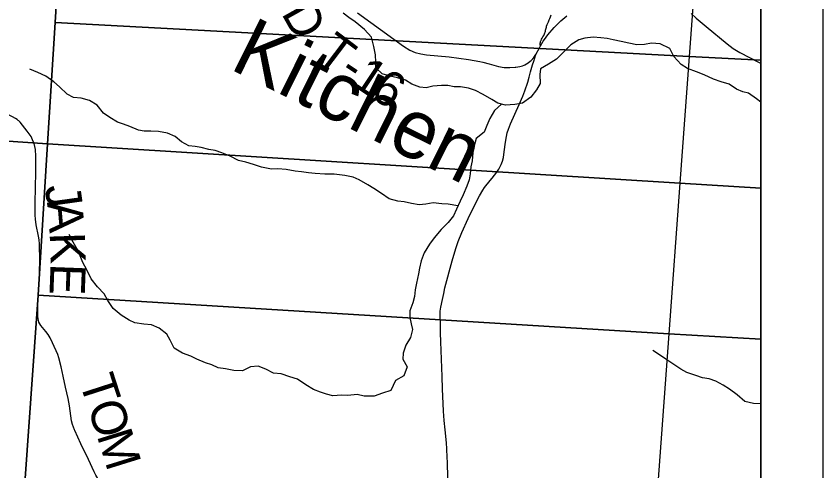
# Model space of a CAD drawing. Extents: x 39.8 to 73.8, y 13 to 35.
# Drawn here: x 47.463 to 48.763, y 31.47 to 32.203 of the extents above; entities that cross this region are included whole.
import ezdxf

# ---------------------------------------------------------------- set-up
doc = ezdxf.new("R2010")
doc.units = 0
for name, color, linetype in [('GM_X_Corporation', 7, 'Continuous'), ('GM_X_Minor_River', 7, 'Continuous'), ('GM_X_Minor_River_Text', 7, 'Continuous'), ('GM_X_Township_Road', 7, 'Continuous'), ('GM_X_Township_Road_Text', 7, 'Continuous'), ('SH_Data', 7, 'Continuous')]:
    doc.layers.add(name, color=color, linetype=linetype)

msp = doc.modelspace()

# ---------------------------------------------------------------- linework, layer by layer
at = {"layer": 'GM_X_Corporation'}
msp.add_lwpolyline([(47.095, 27.8783), (47.5149, 27.8498), (47.5414, 27.8484), (48.663, 27.7809), (48.663, 33.865), (43.6158, 33.865)], dxfattribs=at)
for points in [[(47.5774, 33.0099), (47.5501, 32.582), (47.5261, 32.1933), (47.514, 31.9975), (46.4973, 32.0662), (46.5718, 33.0824)], [(47.5501, 32.582), (48.5754, 32.5153), (48.5476, 32.1383), (47.5261, 32.1933)], [(48.663, 32.1321), (48.663, 32.5097), (48.5754, 32.5153), (48.5476, 32.1383)], [(48.5476, 32.1383), (48.5326, 31.9341), (47.514, 31.9975), (47.5261, 32.1933)], [(48.663, 31.9259), (48.663, 32.1321), (48.5476, 32.1383), (48.5326, 31.9341)], [(46.4973, 32.0662), (47.514, 31.9975), (47.4987, 31.7536), (47.4692, 31.3373), (47.4415, 30.9593), (47.2622, 30.9716), (46.8571, 31.0001), (46.4309, 31.0306)], [(48.5326, 31.9341), (48.5148, 31.6913), (47.4987, 31.7536), (47.514, 31.9975)], [(48.663, 31.6829), (48.663, 31.9259), (48.5326, 31.9341), (48.5148, 31.6913)], [(47.4987, 31.7536), (48.5148, 31.6913), (48.4841, 31.2738), (47.4692, 31.3373)], [(48.663, 31.2629), (48.663, 31.6829), (48.5148, 31.6913), (48.4841, 31.2738)]]:
    msp.add_lwpolyline(points, close=True, dxfattribs=at)
at = {"layer": 'GM_X_Minor_River'}
for p, q in [((47.4985, 32.1125), (47.4856, 32.1181)), ((47.511, 32.1068), (47.4985, 32.1125)), ((47.5239, 32.0974), (47.511, 32.1068)), ((47.5334, 32.0894), (47.5239, 32.0974)), ((47.5456, 32.0773), (47.5334, 32.0894)), ((47.5555, 32.0724), (47.5456, 32.0773)), ((47.568, 32.0713), (47.5555, 32.0724)), ((47.5816, 32.0672), (47.568, 32.0713)), ((47.5938, 32.0597), (47.5816, 32.0672)), ((47.604, 32.0468), (47.5938, 32.0597)), ((48.2341, 32.0511), (48.2266, 32.0385)), ((48.2453, 32.0614), (48.2341, 32.0511)), ((47.6143, 32.04), (47.604, 32.0468)), ((47.6268, 32.0325), (47.6143, 32.04)), ((48.2266, 32.0385), (48.2217, 32.0268)), ((47.6363, 32.0294), (47.6268, 32.0325)), ((47.6466, 32.0253), (47.6363, 32.0294)), ((47.6602, 32.0197), (47.6466, 32.0253)), ((48.2217, 32.0268), (48.2172, 32.0165)), ((47.6697, 32.0178), (47.6602, 32.0197)), ((47.6803, 32.0178), (47.6697, 32.0178)), ((47.6928, 32.0175), (47.6803, 32.0178)), ((47.7072, 32.0145), (47.6928, 32.0175)), ((47.7193, 32.0092), (47.7072, 32.0145)), ((48.2172, 32.0165), (48.2044, 32.0062)), ((47.7296, 32.0005), (47.7193, 32.0092)), ((47.7417, 31.9941), (47.7296, 32.0005)), ((48.2044, 32.0062), (48.2011, 31.9941)), ((47.7516, 31.9934), (47.7417, 31.9941)), ((47.7614, 31.9915), (47.7516, 31.9934)), ((47.7736, 31.9885), (47.7614, 31.9915)), ((47.7842, 31.9867), (47.7736, 31.9885)), ((47.7948, 31.9829), (47.7842, 31.9867)), ((48.2011, 31.9941), (48.1992, 31.9834)), ((47.8081, 31.9776), (47.7948, 31.9829)), ((47.8214, 31.9709), (47.8081, 31.9776)), ((48.1992, 31.9834), (48.1978, 31.9702)), ((47.8335, 31.9679), (47.8214, 31.9709)), ((47.8456, 31.9641), (47.8335, 31.9679)), ((47.8585, 31.96), (47.8456, 31.9641)), ((47.8748, 31.9566), (47.8585, 31.96)), ((48.1959, 31.9607), (48.1948, 31.9493)), ((48.1978, 31.9702), (48.1959, 31.9607)), ((47.885, 31.9574), (47.8748, 31.9566)), ((47.8983, 31.9559), (47.885, 31.9574)), ((47.9131, 31.9533), (47.8983, 31.9559)), ((47.9233, 31.9522), (47.9131, 31.9533)), ((47.9343, 31.9507), (47.9233, 31.9522)), ((47.9449, 31.9496), (47.9343, 31.9507)), ((47.9608, 31.9485), (47.9449, 31.9496)), ((47.9756, 31.9486), (47.9608, 31.9485)), ((47.993, 31.9467), (47.9756, 31.9486)), ((48.0063, 31.9438), (47.993, 31.9467)), ((48.1948, 31.9493), (48.1933, 31.9394)), ((48.0157, 31.9396), (48.0063, 31.9438)), ((48.0298, 31.9313), (48.0157, 31.9396)), ((48.1933, 31.9394), (48.1896, 31.9292)), ((48.0397, 31.9257), (48.0298, 31.9313)), ((48.0518, 31.9173), (48.0397, 31.9257)), ((48.1896, 31.9292), (48.1836, 31.9151)), ((48.0643, 31.909), (48.0518, 31.9173)), ((48.0784, 31.9053), (48.0643, 31.909)), ((48.1836, 31.9151), (48.1787, 31.9052)), ((48.0882, 31.9042), (48.0784, 31.9053)), ((48.1, 31.9012), (48.0882, 31.9042)), ((48.1125, 31.8993), (48.1, 31.9012)), ((48.1231, 31.9001), (48.1125, 31.8993)), ((48.1352, 31.9024), (48.1231, 31.9001)), ((48.1492, 31.901), (48.1352, 31.9024)), ((48.1594, 31.9002), (48.1492, 31.901)), ((48.1751, 31.8975), (48.1594, 31.9002)), ((48.1787, 31.9052), (48.1727, 31.8923)), ((48.1678, 31.8813), (48.1592, 31.871)), ((48.1727, 31.8923), (48.1678, 31.8813)), ((48.1592, 31.871), (48.1483, 31.8592)), ((48.1483, 31.8592), (48.1366, 31.8459)), ((47.5553, 31.8388), (47.5485, 31.8513)), ((48.1366, 31.8459), (48.129, 31.836)), ((47.563, 31.8251), (47.5553, 31.8388)), ((48.129, 31.836), (48.1208, 31.8216)), ((47.5706, 31.8062), (47.563, 31.8251)), ((48.1208, 31.8216), (48.1159, 31.8091)), ((47.5771, 31.7944), (47.5706, 31.8062)), ((48.1159, 31.8091), (48.1129, 31.7973)), ((47.584, 31.7801), (47.5771, 31.7944)), ((48.1129, 31.7973), (48.1114, 31.7878)), ((47.5943, 31.7668), (47.584, 31.7801)), ((48.1114, 31.7878), (48.1081, 31.773)), ((47.6049, 31.7558), (47.5943, 31.7668)), ((48.1081, 31.773), (48.1059, 31.762)), ((47.611, 31.7449), (47.6049, 31.7558)), ((48.1052, 31.7517), (48.1022, 31.7415)), ((48.1059, 31.762), (48.1052, 31.7517)), ((47.6198, 31.7324), (47.611, 31.7449)), ((48.1022, 31.7415), (48.0977, 31.7286)), ((47.6323, 31.7214), (47.6198, 31.7324)), ((48.0977, 31.7286), (48.0977, 31.7176)), ((47.6452, 31.7131), (47.6323, 31.7214)), ((47.6547, 31.7093), (47.6452, 31.7131)), ((48.0977, 31.7176), (48.0997, 31.7077)), ((47.6691, 31.7071), (47.6547, 31.7093)), ((47.6816, 31.7056), (47.6691, 31.7071)), ((47.6938, 31.7007), (47.6816, 31.7056)), ((47.7063, 31.6909), (47.6938, 31.7007)), ((48.0997, 31.7077), (48.1016, 31.6982)), ((47.7113, 31.6811), (47.7063, 31.6909)), ((48.1016, 31.6982), (48.0986, 31.6853)), ((47.7181, 31.6682), (47.7113, 31.6811)), ((48.0911, 31.6732), (48.0866, 31.6603)), ((48.0986, 31.6853), (48.0911, 31.6732)), ((47.7314, 31.6599), (47.7181, 31.6682)), ((48.0866, 31.6603), (48.0863, 31.6504)), ((48.4998, 31.6574), (48.4888, 31.6646)), ((47.7447, 31.6554), (47.7314, 31.6599)), ((47.7546, 31.6505), (47.7447, 31.6554)), ((47.7682, 31.6445), (47.7546, 31.6505)), ((48.0863, 31.6504), (48.0935, 31.6379)), ((48.5115, 31.6495), (48.4998, 31.6574)), ((48.5343, 31.6344), (48.5115, 31.6495)), ((47.7788, 31.6415), (47.7682, 31.6445)), ((47.7887, 31.6366), (47.7788, 31.6415)), ((47.8005, 31.6347), (47.7887, 31.6366)), ((47.8141, 31.6321), (47.8005, 31.6347)), ((47.841, 31.6382), (47.8281, 31.6318)), ((47.8531, 31.6394), (47.841, 31.6382)), ((47.8656, 31.6345), (47.8531, 31.6394)), ((47.8781, 31.6277), (47.8656, 31.6345)), ((48.0935, 31.6379), (48.0879, 31.6238)), ((48.5438, 31.6291), (48.5343, 31.6344)), ((47.8281, 31.6318), (47.8141, 31.6321)), ((47.8902, 31.6266), (47.8781, 31.6277)), ((47.9043, 31.6221), (47.8902, 31.6266)), ((47.9168, 31.6184), (47.9043, 31.6221)), ((48.0879, 31.6238), (48.0743, 31.6162)), ((48.5582, 31.6242), (48.5438, 31.6291)), ((48.5692, 31.6204), (48.5582, 31.6242)), ((47.9301, 31.6093), (47.9168, 31.6184)), ((47.9426, 31.6018), (47.9301, 31.6093)), ((48.0743, 31.6162), (48.0668, 31.5999)), ((48.5798, 31.6186), (48.5692, 31.6204)), ((48.5908, 31.6152), (48.5798, 31.6186)), ((48.6026, 31.6084), (48.5908, 31.6152)), ((48.6125, 31.602), (48.6026, 31.6084)), ((47.9536, 31.5972), (47.9426, 31.6018)), ((47.9631, 31.5942), (47.9536, 31.5972)), ((48.0536, 31.5957), (48.04, 31.5911)), ((48.0668, 31.5999), (48.0536, 31.5957)), ((48.625, 31.5929), (48.6125, 31.602)), ((47.9737, 31.5916), (47.9631, 31.5942)), ((47.9877, 31.5924), (47.9737, 31.5916)), ((47.9979, 31.5921), (47.9877, 31.5924)), ((48.0127, 31.5933), (47.9979, 31.5921)), ((48.0241, 31.591), (48.0127, 31.5933)), ((48.04, 31.5911), (48.0241, 31.591)), ((48.6375, 31.5823), (48.625, 31.5929)), ((48.6512, 31.579), (48.6375, 31.5823)), ((48.663, 31.5784), (48.6512, 31.579))]:
    msp.add_line(p, q, dxfattribs=at)
for points in [[(48.4756, 32.1577), (48.4632, 32.1573), (48.4506, 32.1595), (48.4378, 32.1625), (48.4249, 32.1651), (48.4154, 32.1673), (48.4052, 32.1681), (48.393, 32.1695), (48.3794, 32.1676), (48.3696, 32.1649), (48.3571, 32.1569), (48.3451, 32.1455), (48.3341, 32.1341), (48.3209, 32.1257), (48.3081, 32.1184), (48.307, 32.109), (48.3074, 32.0949), (48.3014, 32.0847), (48.2927, 32.0725), (48.2791, 32.063), (48.2667, 32.061), (48.2515, 32.0598), (48.2394, 32.0628), (48.2299, 32.0689), (48.2155, 32.0772), (48.2033, 32.0836), (48.1923, 32.087), (48.1791, 32.0892), (48.1688, 32.0896), (48.159, 32.0918), (48.1488, 32.0918), (48.1344, 32.0902), (48.1238, 32.0879), (48.1139, 32.089), (48.1007, 32.0935), (48.0908, 32.1003), (48.0779, 32.1041), (48.0658, 32.1067), (48.0529, 32.1104), (48.043, 32.1199), (48.043, 32.1294), (48.0425, 32.1407), (48.0394, 32.1544), (48.0356, 32.1692), (48.0246, 32.182), (48.0097, 32.1941), (47.9995, 32.2009), (47.99, 32.2081)], [(48.663, 32.0649), (48.6559, 32.0699), (48.6434, 32.0793), (48.6339, 32.0815), (48.624, 32.0857), (48.6122, 32.0936), (48.5994, 32.0974), (48.5868, 32.1015), (48.572, 32.1087), (48.5595, 32.1136), (48.5451, 32.1188), (48.5349, 32.1252), (48.5227, 32.1381), (48.5162, 32.1513), (48.5006, 32.1585), (48.487, 32.1596), (48.4756, 32.1577)]]:
    msp.add_lwpolyline(points, dxfattribs=at)
at = {"layer": 'GM_X_Township_Road'}
for points in [[(48.0135, 32.2089), (48.0346, 32.1933), (48.0871, 32.1549), (48.0977, 32.1485), (48.1062, 32.1448), (48.1152, 32.1423), (48.1244, 32.1408), (48.1612, 32.1376), (48.192, 32.1337), (48.2102, 32.1303), (48.2153, 32.1289), (48.2252, 32.1262), (48.2402, 32.1222), (48.2494, 32.1207), (48.2585, 32.1205), (48.2675, 32.1209), (48.2681, 32.121), (48.2748, 32.1219), (48.2789, 32.1231), (48.2815, 32.1242), (48.2828, 32.1248), (48.2881, 32.1278), (48.2916, 32.1306), (48.2932, 32.132), (48.2971, 32.1364), (48.3006, 32.1415), (48.3063, 32.1525), (48.308, 32.1553), (48.3126, 32.1632), (48.3146, 32.1659), (48.3199, 32.1732), (48.33, 32.185), (48.3409, 32.196), (48.3505, 32.2039)], [(48.5508, 32.2078), (48.5587, 32.1998), (48.5751, 32.1864), (48.6086, 32.1586), (48.6186, 32.1513), (48.6292, 32.1448), (48.6595, 32.1292), (48.663, 32.1272)], [(48.308, 32.1553), (48.3077, 32.1568), (48.3076, 32.1584), (48.3077, 32.1598), (48.3079, 32.1611), (48.3082, 32.1623), (48.3087, 32.1637), (48.3089, 32.1642), (48.3099, 32.1663), (48.3107, 32.1678), (48.312, 32.17), (48.3132, 32.172), (48.314, 32.1734), (48.3147, 32.1748), (48.3152, 32.1762), (48.3157, 32.1776), (48.3161, 32.1789), (48.3164, 32.1805), (48.3168, 32.1824), (48.3172, 32.1841), (48.3175, 32.1858), (48.318, 32.1874), (48.3188, 32.1897), (48.3197, 32.192), (48.3207, 32.1942), (48.3223, 32.1975), (48.3233, 32.1997), (48.3243, 32.2022), (48.3255, 32.2054)], [(48.1592, 31.4396), (48.1583, 31.4831), (48.1573, 31.5045), (48.1571, 31.5061), (48.1564, 31.5159), (48.1543, 31.5368), (48.1529, 31.5519), (48.1519, 31.5669), (48.1501, 31.6029), (48.1497, 31.6226), (48.1481, 31.6645), (48.1477, 31.6783), (48.1472, 31.6928), (48.1468, 31.7058), (48.1463, 31.72), (48.1466, 31.7281), (48.1477, 31.7345), (48.1503, 31.7468), (48.1521, 31.7564), (48.1542, 31.7653), (48.1657, 31.8089), (48.1717, 31.829), (48.1757, 31.8403), (48.1816, 31.8546), (48.1918, 31.8773), (48.2029, 31.9004), (48.21, 31.9138), (48.215, 31.9227), (48.218, 31.927), (48.2272, 31.9382), (48.2301, 31.9422), (48.2377, 31.9519), (48.2412, 31.9568), (48.2449, 31.9644), (48.2468, 31.9697), (48.2483, 31.9755), (48.2498, 31.9847), (48.2516, 32), (48.2531, 32.0091), (48.2545, 32.0151), (48.2563, 32.021), (48.2596, 32.0296), (48.2736, 32.0607), (48.2796, 32.0742), (48.2829, 32.0827), (48.2875, 32.0967), (48.29, 32.1051), (48.2904, 32.1071), (48.2922, 32.1136), (48.2932, 32.1173), (48.2954, 32.125), (48.2974, 32.1309), (48.3006, 32.1415)], [(47.4666, 32.0352), (47.465, 32.0365), (47.4625, 32.0382), (47.4573, 32.0412), (47.4491, 32.0453), (47.4348, 32.0515), (47.4205, 32.0571), (47.4061, 32.063), (47.3481, 32.0884)], [(47.5579, 31.5358), (47.5575, 31.5367), (47.5543, 31.5453), (47.5527, 31.5512), (47.5491, 31.5754), (47.5473, 31.5872), (47.543, 31.6053), (47.5392, 31.6232), (47.536, 31.638), (47.5321, 31.6526), (47.5303, 31.6579), (47.522, 31.6766), (47.5179, 31.685), (47.5147, 31.6903), (47.5111, 31.6953), (47.5032, 31.7048), (47.5015, 31.7073), (47.5001, 31.7101), (47.4991, 31.713), (47.4986, 31.716), (47.4984, 31.7191), (47.4985, 31.7283), (47.4983, 31.7376), (47.4984, 31.7438), (47.4991, 31.7531), (47.5004, 31.7748), (47.5013, 31.809), (47.5009, 31.8363), (47.5004, 31.8426), (47.4995, 31.8486), (47.4958, 31.867), (47.4945, 31.8762), (47.4942, 31.8824), (47.4942, 31.8886), (47.4941, 31.8917), (47.4939, 31.8979), (47.4942, 31.901), (47.4941, 31.9068), (47.4945, 31.9228), (47.4952, 31.9564), (47.4953, 31.9775), (47.4943, 31.9883), (47.4934, 31.9934), (47.4925, 31.9978), (47.4898, 32.0041), (47.4874, 32.0091), (47.4812, 32.0181), (47.4738, 32.0278), (47.4697, 32.0325), (47.4675, 32.0346), (47.4666, 32.0352)], [(47.6523, 31.3837), (47.642, 31.3992), (47.633, 31.4119), (47.6235, 31.4241), (47.6174, 31.4312), (47.6063, 31.4436), (47.5983, 31.4532), (47.5948, 31.4583), (47.5917, 31.4636), (47.5889, 31.4691), (47.58, 31.489), (47.5677, 31.5141), (47.5579, 31.5358)]]:
    msp.add_lwpolyline(points, dxfattribs=at)
at = {"layer": 'SH_Data'}
for p, q in [((48.763, 33.965), (48.763, 26.965)), ((48.663, 33.865), (48.663, 27.065))]:
    msp.add_line(p, q, dxfattribs=at)

# ---------------------------------------------------------------- texts
at = {"layer": 'GM_X_Minor_River_Text'}
msp.add_text('Kitchen', height=0.0947, rotation=333.6427, dxfattribs=at).set_placement((47.8052, 32.1191))
at = {"layer": 'GM_X_Township_Road_Text'}
for s, rotation, p in [('D', 299.2689, (47.8898, 32.2081)), ('T', 322.8095, (47.9444, 32.1353)), ('1', 326.4217, (48.0009, 32.0943)), ('-', 326.1684, (47.9813, 32.1075)), ('6', 327.744, (48.0312, 32.0742)), ('J', 277.935, (47.5094, 31.9289)), ('A', 274.9237, (47.513, 31.9032)), ('K', 271.8655, (47.5173, 31.8542)), ('E', 267.8567, (47.5189, 31.8053)), ('T', 287.9132, (47.5645, 31.6156)), ('O', 287.9176, (47.5775, 31.5751)), ('M', 287.286, (47.5929, 31.5277))]:
    msp.add_text(s, height=0.0568, rotation=rotation, dxfattribs=at).set_placement(p)

doc.saveas('drawing.dxf')
